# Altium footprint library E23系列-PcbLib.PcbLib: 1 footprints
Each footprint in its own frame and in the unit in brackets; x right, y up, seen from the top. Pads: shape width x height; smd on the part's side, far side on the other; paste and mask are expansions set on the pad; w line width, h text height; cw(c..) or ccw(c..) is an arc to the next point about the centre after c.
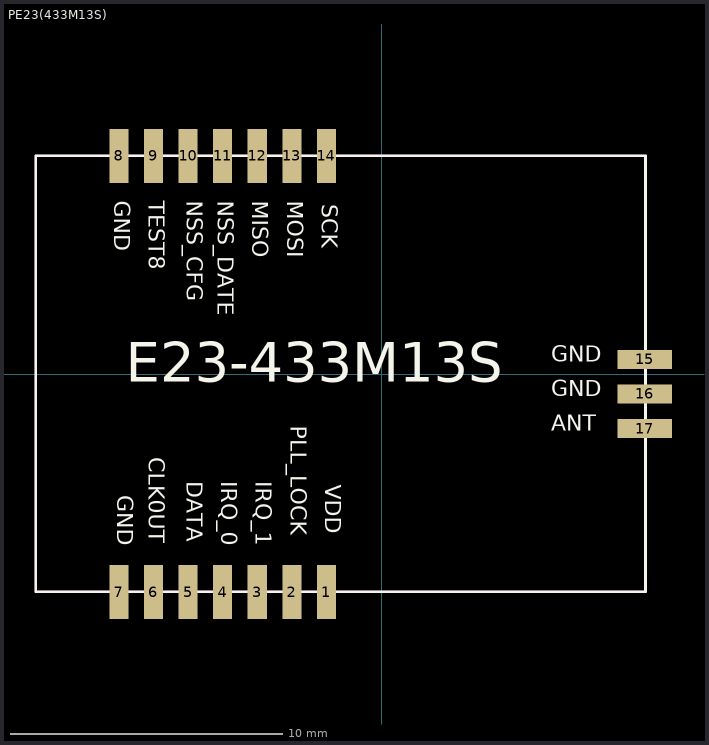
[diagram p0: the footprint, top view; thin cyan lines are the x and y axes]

## PE23(433M13S) [mm] "22.6mm*16.1mm*2.5mm-S"
pads (17):
  rect 0.7x2 smd: 1(-2.034,-8.001) 2(-3.304,-8.001) 3(-4.574,-8.001) 4(-5.844,-8.001) 5(-7.114,-8.001) 6(-8.384,-8.001) 7(-9.654,-8.001) 8(-9.654,8.001) 9(-8.384,8.001) 10(-7.114,8.001) 11(-5.844,8.001) 12(-4.574,8.001) 13(-3.304,8.001) 14(-2.034,8.001)
  rect 2x0.7 smd: 15(9.654,0.537) 16(9.654,-0.733) 17(9.654,-2.003)
Top Overlay:
  lines w0.1: 0.255,-7.992 9.676,-7.992 9.676,8.013 -12.702,8.013 -12.702,-7.992 0.382,-7.992
  text "GND" at -10.033,6.35 h1
  text "TEST8" at -8.763,6.35 h1
  text "NSS_CFG" at -7.366,6.35 h1
  text "NSS_DATE" at -6.223,6.35 h1
  text "MISO" at -4.953,6.35 h1
  text "MOSI" at -3.683,6.35 h1
  text "SCK" at -2.413,6.223 h1
  text "VDD" at -2.286,-4.064 h1
  text "PLL_LOCK" at -3.556,-1.905 h1
  text "IRQ_1" at -4.826,-3.937 h1
  text "IRQ_0" at -6.096,-3.937 h1
  text "DATA" at -7.366,-3.937 h1
  text "CLK0UT" at -8.763,-3.048 h1
  text "GND" at -9.906,-4.445 h1
  text "GND" at 6.223,-1.016 h1
  text "GND" at 6.223,0.254 h1
  text "ANT" at 6.223,-2.286 h1
  text "E23-433M13S" at -9.398,-0.762 h2.5
Keep-Out Layer:
  lines w0.1: -12.702,-7.992 9.676,-7.992 9.676,8.013 -12.702,8.013 -12.702,-7.992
